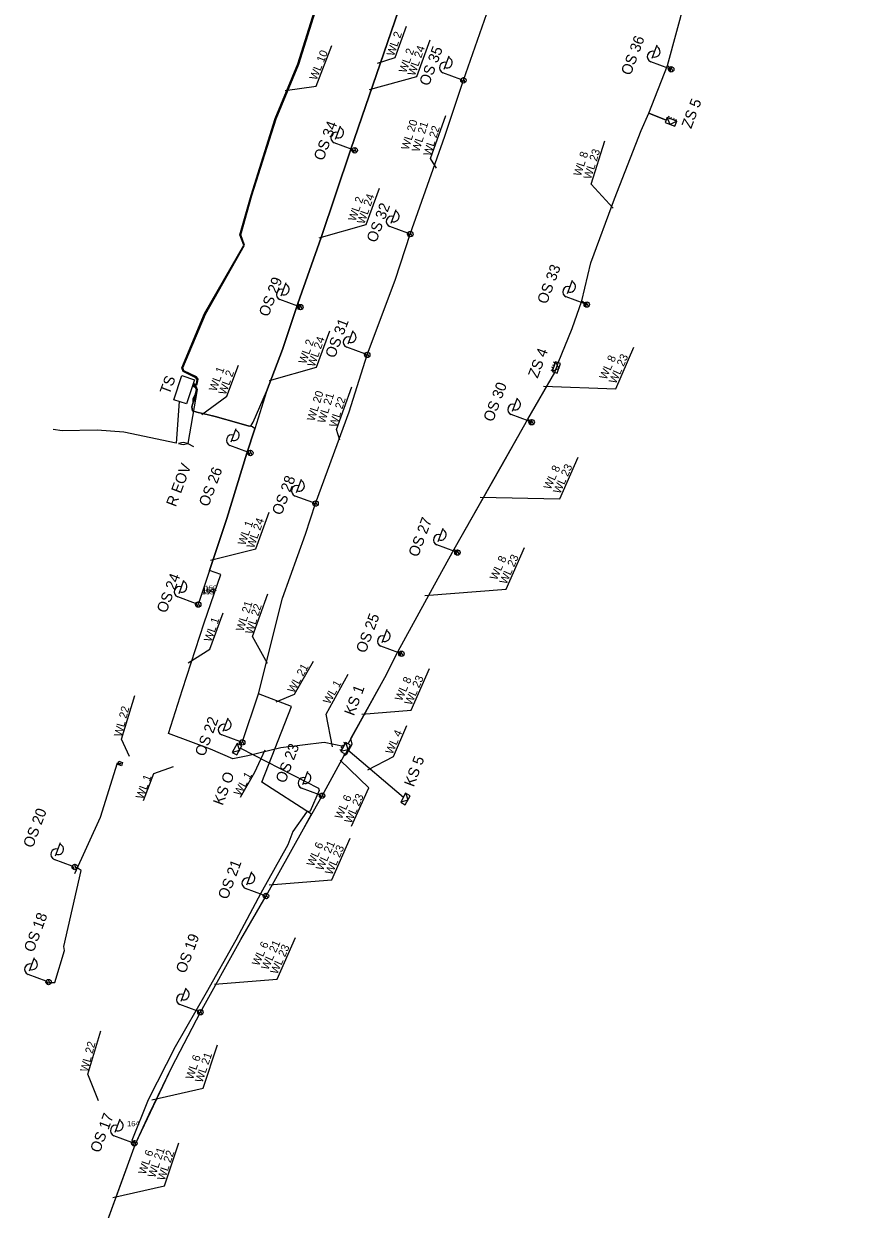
# Model space of a CAD drawing. Extents: x -695448 to -695200, y -1124997 to -1123857.
# Drawn here: x -695445.5 to -695287.6, y -1124601.1 to -1124378.9 of the extents above; entities that cross this region are included whole.
import ezdxf

# ---------------------------------------------------------------- set-up
doc = ezdxf.new("R2010")
doc.units = 0
doc.layers.add('Vrstva 26', color=7, linetype='Continuous')

msp = doc.modelspace()

# ---------------------------------------------------------------- linework, layer by layer
at = {"layer": 'Vrstva 26'}
for p, q in [((-695327.74, -1124385.33), (-695326.82, -1124382.84)), ((-695366.68, -1124387.38), (-695365.75, -1124384.89)), ((-695324.64, -1124387.24), (-695327.99, -1124386)), ((-695324.16, -1124387.42), (-695324.84, -1124386.71)), ((-695324.19, -1124387.93), (-695324.56, -1124387.11)), ((-695323.82, -1124387.8), (-695324.23, -1124386.92)), ((-695363.57, -1124389.3), (-695366.92, -1124388.06)), ((-695363.12, -1124389.98), (-695363.49, -1124389.17)), ((-695362.75, -1124389.86), (-695363.16, -1124388.97)), ((-695387.05, -1124400.51), (-695386.12, -1124398.01)), ((-695383.94, -1124402.42), (-695387.29, -1124401.18)), ((-695384.22, -1124402.55), (-695383.46, -1124402.6)), ((-695383.49, -1124403.11), (-695383.86, -1124402.29)), ((-695383.12, -1124402.98), (-695383.53, -1124402.09)), ((-695376.63, -1124416.21), (-695375.71, -1124413.71)), ((-695373.52, -1124418.12), (-695376.88, -1124416.88)), ((-695373.07, -1124418.81), (-695373.45, -1124417.99)), ((-695372.71, -1124418.68), (-695373.12, -1124417.79)), ((-695397.22, -1124429.89), (-695396.3, -1124427.39)), ((-695343.58, -1124429.4), (-695342.66, -1124426.9)), ((-695394.11, -1124431.8), (-695397.47, -1124430.56)), ((-695394.1, -1124431.3), (-695393.64, -1124431.98)), ((-695393.66, -1124432.49), (-695394.04, -1124431.67)), ((-695393.3, -1124432.36), (-695393.71, -1124431.47)), ((-695340.47, -1124431.31), (-695343.83, -1124430.07)), ((-695340.91, -1124430.82), (-695339.99, -1124431.49)), ((-695340.02, -1124432), (-695340.4, -1124431.18)), ((-695339.66, -1124431.87), (-695340.07, -1124430.98)), ((-695384.7, -1124438.83), (-695383.78, -1124436.34)), ((-695381.59, -1124440.74), (-695384.95, -1124439.5)), ((-695381.14, -1124441.43), (-695381.52, -1124440.61)), ((-695380.78, -1124441.3), (-695381.19, -1124440.41)), ((-695353.89, -1124451.46), (-695352.97, -1124448.96)), ((-695350.78, -1124453.37), (-695354.14, -1124452.13)), ((-695351, -1124452.98), (-695350.3, -1124453.55)), ((-695350.33, -1124454.06), (-695350.71, -1124453.24)), ((-695349.97, -1124453.93), (-695350.38, -1124453.04)), ((-695406.6, -1124457.22), (-695405.67, -1124454.73)), ((-695403.49, -1124459.13), (-695406.84, -1124457.89)), ((-695402.67, -1124459.7), (-695403.08, -1124458.81)), ((-695403.64, -1124459.33), (-695403.01, -1124459.31)), ((-695403.04, -1124459.82), (-695403.41, -1124459.01)), ((-695394.39, -1124466.7), (-695393.46, -1124464.21)), ((-695391.28, -1124468.62), (-695394.63, -1124467.38)), ((-695390.83, -1124469.3), (-695391.2, -1124468.49)), ((-695390.46, -1124469.18), (-695390.87, -1124468.29)), ((-695367.8, -1124475.88), (-695366.88, -1124473.38)), ((-695364.69, -1124477.79), (-695368.05, -1124476.55)), ((-695364.83, -1124477.32), (-695364.22, -1124477.97)), ((-695364.24, -1124478.48), (-695364.62, -1124477.66)), ((-695363.88, -1124478.35), (-695364.29, -1124477.46)), ((-695416.37, -1124485.63), (-695415.45, -1124483.14)), ((-695413.26, -1124487.54), (-695416.62, -1124486.3)), ((-695412.81, -1124488.23), (-695413.19, -1124487.41)), ((-695412.45, -1124488.1), (-695412.86, -1124487.21)), ((-695378.3, -1124494.86), (-695377.38, -1124492.36)), ((-695375.19, -1124496.77), (-695378.55, -1124495.53)), ((-695375.29, -1124496.44), (-695374.71, -1124496.95)), ((-695374.74, -1124497.46), (-695375.12, -1124496.64)), ((-695374.38, -1124497.33), (-695374.79, -1124496.44)), ((-695408.12, -1124511.47), (-695407.19, -1124508.97)), ((-695405.01, -1124513.38), (-695408.36, -1124512.14)), ((-695404.56, -1124514.07), (-695404.93, -1124513.25)), ((-695404.19, -1124513.94), (-695404.6, -1124513.05)), ((-695384.73, -1124514.92), (-695374.35, -1124523.84)), ((-695393.16, -1124521.46), (-695392.24, -1124518.97)), ((-695390.05, -1124523.37), (-695393.41, -1124522.13)), ((-695389.6, -1124524.06), (-695389.98, -1124523.24)), ((-695389.24, -1124523.94), (-695389.65, -1124523.05)), ((-695439.49, -1124534.82), (-695438.57, -1124532.32)), ((-695436.38, -1124536.73), (-695439.74, -1124535.49)), ((-695435.93, -1124537.42), (-695436.31, -1124536.6)), ((-695435.57, -1124537.29), (-695435.98, -1124536.4)), ((-695403.66, -1124540.25), (-695402.74, -1124537.75)), ((-695400.56, -1124542.16), (-695403.91, -1124540.92)), ((-695400.11, -1124542.85), (-695400.48, -1124542.03)), ((-695399.74, -1124542.72), (-695400.15, -1124541.83)), ((-695444.4, -1124556.38), (-695443.48, -1124553.89)), ((-695441.29, -1124558.29), (-695444.65, -1124557.05)), ((-695440.84, -1124558.98), (-695441.22, -1124558.16)), ((-695440.48, -1124558.85), (-695440.89, -1124557.97)), ((-695415.96, -1124562.03), (-695415.04, -1124559.54)), ((-695412.85, -1124563.94), (-695416.21, -1124562.7)), ((-695412.4, -1124564.63), (-695412.78, -1124563.82)), ((-695412.04, -1124564.51), (-695412.45, -1124563.62)), ((-695428.33, -1124586.6), (-695427.41, -1124584.11)), ((-695425.22, -1124588.51), (-695428.58, -1124587.27)), ((-695424.77, -1124589.2), (-695425.15, -1124588.38)), ((-695424.41, -1124589.07), (-695424.82, -1124588.19))]:
    msp.add_line(p, q, dxfattribs=at)
for points in [[(-695325.09, -1124396.92), (-695328.34, -1124395.64), (-695324.84, -1124386.71), (-695321.56, -1124374.49), (-695315.29, -1124355.96), (-695310.83, -1124340.54), (-695308.31, -1124332.94), (-695298.45, -1124305.03), (-695295.16, -1124294), (-695287.62, -1124268.59), (-695300.31, -1124263.86), (-695308.19, -1124258.46), (-695311.18, -1124257.36)], [(-695390.8, -1124468.79), (-695384.48, -1124451.59), (-695381.11, -1124440.92), (-695375.83, -1124426.72), (-695373.04, -1124418.3), (-695366.56, -1124399.91), (-695363.09, -1124389.47), (-695356.09, -1124369.39), (-695352.55, -1124358.94), (-695351.13, -1124358.25), (-695350.8, -1124357.25)], [(-695413.68, -1124446.27), (-695413.27, -1124446.44), (-695413.12, -1124446.31), (-695412.98, -1124445.52), (-695413.24, -1124445.21), (-695415.63, -1124444.02), (-695415.86, -1124443.36), (-695411.6, -1124433.2), (-695404.26, -1124420.34), (-695404.96, -1124418.42), (-695402.89, -1124411.01), (-695398.35, -1124396.64), (-695394.13, -1124386.36), (-695385.53, -1124359.11)], [(-695413.74, -1124446.44), (-695413.24, -1124446.63), (-695412.97, -1124446.41), (-695412.8, -1124445.48), (-695413.13, -1124445.07), (-695415.49, -1124443.9), (-695415.68, -1124443.36), (-695411.44, -1124433.27), (-695404.08, -1124420.35), (-695404.78, -1124418.42), (-695402.71, -1124411.05), (-695398.18, -1124396.7), (-695393.96, -1124386.42), (-695385.36, -1124359.17)], [(-695432.64, -1124611.07), (-695427.6, -1124597.21), (-695424.56, -1124588.76), (-695421.94, -1124583.2), (-695417.73, -1124574.39), (-695412.37, -1124564.12), (-695404.77, -1124550.51), (-695400.08, -1124542.34), (-695393.08, -1124529.78), (-695391.53, -1124527.03), (-695400.84, -1124520.99), (-695395.33, -1124506.85), (-695401.46, -1124504.46), (-695396.99, -1124486.5), (-695392.71, -1124474.55), (-695390.8, -1124468.79), (-695384.48, -1124451.59), (-695381.11, -1124440.92), (-695375.83, -1124426.72), (-695373.04, -1124418.3), (-695366.56, -1124399.91), (-695363.09, -1124389.47), (-695356.09, -1124369.39)], [(-695404.53, -1124513.56), (-695401.46, -1124504.46), (-695396.99, -1124486.5), (-695392.71, -1124474.55), (-695390.8, -1124468.79), (-695384.48, -1124451.59), (-695381.11, -1124440.92), (-695375.83, -1124426.72), (-695373.04, -1124418.3), (-695366.56, -1124399.91), (-695363.09, -1124389.47), (-695356.09, -1124369.39)], [(-695413.77, -1124450.05), (-695413.97, -1124450.66), (-695413.88, -1124451.4), (-695413.01, -1124451.69), (-695411.66, -1124451.99), (-695410.63, -1124452.22), (-695409.6, -1124452.45), (-695405.19, -1124453.71), (-695403.24, -1124454.27), (-695402.83, -1124454.18), (-695402.48, -1124453.54), (-695399.99, -1124447.81), (-695396.97, -1124439.89), (-695394.1, -1124431.3), (-695389.77, -1124418.94), (-695384.22, -1124402.55), (-695381.37, -1124394.21), (-695374.55, -1124374.32)], [(-695374.55, -1124374.32), (-695384.22, -1124402.55), (-695389.77, -1124418.94), (-695394.1, -1124431.3), (-695396.97, -1124439.89), (-695399.99, -1124447.81), (-695402.2, -1124454.81), (-695403.64, -1124459.33), (-695407.43, -1124471.62), (-695412.78, -1124487.72)], [(-695412.37, -1124564.12), (-695404.77, -1124550.51), (-695400.08, -1124542.34), (-695393.08, -1124529.78), (-695389.57, -1124523.55), (-695385.44, -1124515.98), (-695384.93, -1124515.68), (-695383.96, -1124513.88), (-695384.16, -1124512.85), (-695377.82, -1124501.36), (-695375.29, -1124496.44), (-695367.81, -1124482.77), (-695364.83, -1124477.32), (-695356.03, -1124461.84), (-695351, -1124452.98), (-695345.96, -1124444.22), (-695345.34, -1124442.39), (-695342.7, -1124435.97), (-695340.91, -1124430.82), (-695339.23, -1124423.66), (-695334.81, -1124411.65), (-695329.78, -1124398.88), (-695328.34, -1124395.64), (-695324.84, -1124386.71), (-695321.56, -1124374.49)], [(-695379.16, -1124386.28), (-695375.88, -1124385.19), (-695373.78, -1124379.34)], [(-695396.52, -1124391.37), (-695390.68, -1124390.55), (-695387.73, -1124382.92)], [(-695380.67, -1124391.18), (-695371.81, -1124388.73), (-695369.35, -1124381.88)], [(-695368.11, -1124405.94), (-695369.23, -1124404.11), (-695366.39, -1124396.07)], [(-695345.34, -1124442.39), (-695342.7, -1124435.97), (-695340.91, -1124430.82), (-695339.23, -1124423.66), (-695334.81, -1124411.65), (-695329.78, -1124398.88), (-695328.34, -1124395.64), (-695325.09, -1124396.92)], [(-695323.12, -1124397.12), (-695324.37, -1124397.72), (-695324.91, -1124396.44)], [(-695335.04, -1124413.42), (-695339.15, -1124408.93), (-695336.61, -1124400.79)], [(-695390.15, -1124418.97), (-695381.3, -1124416.51), (-695378.84, -1124409.66)], [(-695399.45, -1124445.72), (-695390.59, -1124443.26), (-695388.13, -1124436.41)], [(-695348.08, -1124446.82), (-695334.56, -1124447.26), (-695331.15, -1124439.45)], [(-695412.1, -1124452.13), (-695407.39, -1124448.67), (-695405.23, -1124442.85)], [(-695345.82, -1124442.24), (-695345.2, -1124443.48), (-695346.47, -1124444.05)], [(-695384.7, -1124513.84), (-695377.82, -1124501.36), (-695375.29, -1124496.44), (-695367.81, -1124482.77), (-695364.83, -1124477.32), (-695351, -1124452.98), (-695345.96, -1124444.22)], [(-695413.8, -1124446.61), (-695413.24, -1124446.81), (-695412.97, -1124447.39), (-695414.71, -1124457.54), (-695413.66, -1124458.1)], [(-695413.85, -1124446.76), (-695413.33, -1124446.95), (-695413.14, -1124447.4), (-695413.77, -1124450.05)], [(-695386.26, -1124456.88), (-695386.88, -1124454.93), (-695384.03, -1124446.9)], [(-695416.32, -1124449.68), (-695416.88, -1124457.45), (-695426.71, -1124455.42), (-695431.7, -1124455.05), (-695438.26, -1124455.15), (-695439.94, -1124454.94)], [(-695385.55, -1124514.33), (-695389.21, -1124513.56), (-695397.27, -1124514.55), (-695403.51, -1124516.08), (-695406.28, -1124516.63), (-695410.5, -1124514.84), (-695418.36, -1124511.88), (-695415.71, -1124503.66), (-695411.68, -1124491.14), (-695408.54, -1124482.07), (-695410.67, -1124481.36), (-695407.43, -1124471.62), (-695403.64, -1124459.33), (-695402.2, -1124454.81), (-695402.6, -1124454.44), (-695403.24, -1124454.27), (-695405.19, -1124453.71), (-695409.6, -1124452.45), (-695413.01, -1124451.69), (-695413.88, -1124451.4), (-695413.97, -1124450.66), (-695413.77, -1124450.05)], [(-695359.94, -1124467.6), (-695345, -1124467.88), (-695341.59, -1124460.07)], [(-695410.47, -1124479.38), (-695401.96, -1124477.26), (-695399.5, -1124470.41)], [(-695370.34, -1124486.03), (-695355.07, -1124484.84), (-695351.66, -1124477.03)], [(-695399.83, -1124498.78), (-695402.6, -1124493.71), (-695399.75, -1124485.68)], [(-695414.68, -1124498.65), (-695410.59, -1124496.11), (-695408.13, -1124489.26)], [(-695398.2, -1124505.96), (-695394.77, -1124504.53), (-695391.2, -1124498.34)], [(-695387.62, -1124514.38), (-695388.79, -1124508.24), (-695384.7, -1124500.77)], [(-695382.13, -1124508.24), (-695372.86, -1124507.51), (-695369.45, -1124499.7)], [(-695425.65, -1124516.22), (-695427.13, -1124512.93), (-695424.65, -1124504.77)], [(-695381.03, -1124518.68), (-695376.21, -1124516.19), (-695373.68, -1124510.39)], [(-695405.5, -1124513.75), (-695405.07, -1124515.06), (-695406.41, -1124515.44)], [(-695385.13, -1124513.59), (-695384.73, -1124514.92), (-695386.07, -1124515.26)], [(-695432.64, -1124611.07), (-695424.56, -1124588.76), (-695417.73, -1124574.39), (-695412.37, -1124564.12), (-695404.77, -1124550.51), (-695400.08, -1124542.34), (-695393.08, -1124529.78), (-695389.57, -1124523.55), (-695385.44, -1124515.98), (-695385.37, -1124515.66)], [(-695404.83, -1124514.62), (-695390.26, -1124522.15), (-695390.12, -1124522.58), (-695391.82, -1124526.44), (-695392.51, -1124526.62), (-695395.03, -1124530.26), (-695395.98, -1124532.78), (-695401.05, -1124541.84), (-695405.76, -1124550.6), (-695411.32, -1124560.47), (-695417.11, -1124570.58), (-695422.17, -1124580.53), (-695425.24, -1124588.17), (-695424.74, -1124588.69)], [(-695404.84, -1124523.83), (-695402.19, -1124519.15), (-695400.25, -1124514.92)], [(-695435.88, -1124538.13), (-695431.11, -1124527.58), (-695427.92, -1124517.39), (-695427.43, -1124517.51)], [(-695423.04, -1124524.42), (-695421.11, -1124519.4), (-695417.43, -1124518.1)], [(-695384.04, -1124529.26), (-695380.79, -1124522.06), (-695386.21, -1124516.91)], [(-695373.91, -1124523.07), (-695373.51, -1124524.39), (-695374.85, -1124524.74)], [(-695399.47, -1124540.22), (-695387.74, -1124539.3), (-695384.33, -1124531.49)], [(-695440.81, -1124558.47), (-695440.18, -1124558.53), (-695439.62, -1124558.54), (-695437.82, -1124552.56), (-695437.97, -1124551.78), (-695434.72, -1124537.55), (-695435.26, -1124537.2), (-695435.9, -1124536.9)], [(-695409.72, -1124558.84), (-695398, -1124557.93), (-695394.58, -1124550.12)], [(-695431.49, -1124580.76), (-695433.49, -1124575.76), (-695431.01, -1124567.61)], [(-695421.5, -1124580.52), (-695411.86, -1124578.34), (-695409.17, -1124570.26)], [(-695428.76, -1124598.85), (-695419.12, -1124596.67), (-695416.42, -1124588.58)]]:
    msp.add_lwpolyline(points, dxfattribs=at)
for points in [[(-695323.12, -1124397.12), (-695324.91, -1124396.44), (-695325.27, -1124397.38), (-695323.47, -1124398.06)], [(-695345.83, -1124442.24), (-695346.47, -1124444.05), (-695345.52, -1124444.38), (-695344.88, -1124442.57)], [(-695417.33, -1124449.35), (-695415.83, -1124444.81), (-695413.46, -1124445.6), (-695414.97, -1124450.13)], [(-695413.38, -1124448.34), (-695413.77, -1124449.15), (-695413.77, -1124450.05), (-695413.39, -1124449.24)], [(-695415.58, -1124457.35), (-695416.46, -1124457.54), (-695415.58, -1124457.73), (-695414.71, -1124457.54)], [(-695405.5, -1124513.75), (-695406.41, -1124515.44), (-695405.52, -1124515.91), (-695404.62, -1124514.22)], [(-695385.14, -1124513.59), (-695386.07, -1124515.26), (-695385.2, -1124515.75), (-695384.26, -1124514.08)], [(-695427.64, -1124517.07), (-695426.95, -1124517.31), (-695427.17, -1124517.95), (-695427.87, -1124517.71)], [(-695373.92, -1124523.06), (-695374.85, -1124524.74), (-695373.98, -1124525.23), (-695373.04, -1124523.55)]]:
    msp.add_lwpolyline(points, close=True, dxfattribs=at)
for centre, radius in [((-695324.16, -1124387.42), 0.511), ((-695324.16, -1124387.42), 0.511), ((-695363.09, -1124389.47), 0.511), ((-695363.09, -1124389.47), 0.511), ((-695383.46, -1124402.6), 0.511), ((-695383.46, -1124402.6), 0.511), ((-695373.04, -1124418.3), 0.511), ((-695373.04, -1124418.3), 0.511), ((-695393.64, -1124431.98), 0.511), ((-695393.64, -1124431.98), 0.511), ((-695339.99, -1124431.49), 0.511), ((-695339.99, -1124431.49), 0.511), ((-695381.11, -1124440.92), 0.511), ((-695381.11, -1124440.92), 0.511), ((-695350.3, -1124453.55), 0.511), ((-695350.3, -1124453.55), 0.511), ((-695403.01, -1124459.31), 0.511), ((-695403.01, -1124459.31), 0.511), ((-695390.8, -1124468.79), 0.511), ((-695390.8, -1124468.79), 0.511), ((-695364.22, -1124477.97), 0.511), ((-695364.22, -1124477.97), 0.511), ((-695412.78, -1124487.72), 0.511), ((-695412.78, -1124487.72), 0.511), ((-695374.71, -1124496.95), 0.511), ((-695374.71, -1124496.95), 0.511), ((-695404.53, -1124513.56), 0.511), ((-695404.53, -1124513.56), 0.511), ((-695427.43, -1124517.51), 0.0949), ((-695389.57, -1124523.55), 0.511), ((-695389.57, -1124523.55), 0.511), ((-695435.9, -1124536.91), 0.511), ((-695435.9, -1124536.91), 0.511), ((-695400.08, -1124542.34), 0.511), ((-695400.08, -1124542.34), 0.511), ((-695440.81, -1124558.47), 0.511), ((-695440.81, -1124558.47), 0.511), ((-695412.37, -1124564.12), 0.511), ((-695412.37, -1124564.12), 0.511), ((-695424.74, -1124588.69), 0.511), ((-695424.74, -1124588.69), 0.511)]:
    msp.add_circle(centre, radius, dxfattribs=at)
for centre, radius, start, end in [((-695327.27, -1124384.09), 1.02, 249.0025, 70.4077), ((-695366.2, -1124386.14), 1.02, 249.0025, 70.4077), ((-695327.64, -1124385.04), 1.02, 69.7051, 249.7051), ((-695366.57, -1124387.1), 1.02, 69.7051, 249.7051), ((-695324.36, -1124396.34), 0.285, 147.18, 350.4135), ((-695323.44, -1124396.69), 0.285, 147.18, 350.4135), ((-695386.57, -1124399.26), 1.02, 249.0025, 70.4077), ((-695386.94, -1124400.22), 1.02, 69.7051, 249.7051), ((-695376.16, -1124414.96), 1.02, 249.0025, 70.4077), ((-695376.52, -1124415.92), 1.02, 69.7051, 249.7051), ((-695396.75, -1124428.65), 1.02, 249.0025, 70.4077), ((-695343.11, -1124428.16), 1.02, 249.0025, 70.4077), ((-695397.12, -1124429.6), 1.02, 69.7051, 249.7051), ((-695343.47, -1124429.11), 1.02, 69.7051, 249.7051), ((-695384.23, -1124437.59), 1.02, 249.0025, 70.4077), ((-695384.59, -1124438.54), 1.02, 69.7051, 249.7051), ((-695346.58, -1124443.49), 0.285, 238.3384, 81.5718), ((-695346.25, -1124442.57), 0.285, 238.3384, 81.5718), ((-695353.42, -1124450.21), 1.02, 249.0025, 70.4077), ((-695353.78, -1124451.17), 1.02, 69.7051, 249.7051), ((-695406.49, -1124456.93), 1.02, 69.7051, 249.7051), ((-695406.12, -1124455.98), 1.02, 249.0025, 70.4077), ((-695394.28, -1124466.42), 1.02, 69.7051, 249.7051), ((-695393.91, -1124465.46), 1.02, 249.0025, 70.4077), ((-695367.33, -1124474.63), 1.02, 249.0025, 70.4077), ((-695367.7, -1124475.59), 1.02, 69.7051, 249.7051), ((-695416.26, -1124485.34), 1.02, 69.7051, 249.7051), ((-695415.9, -1124484.39), 1.02, 249.0025, 70.4077), ((-695378.19, -1124494.57), 1.02, 69.7051, 249.7051), ((-695377.83, -1124493.61), 1.02, 249.0025, 70.4077), ((-695407.64, -1124510.23), 1.02, 249.0025, 70.4077), ((-695408.01, -1124511.18), 1.02, 69.7051, 249.7051), ((-695386.09, -1124514.7), 0.285, 228.5657, 71.7991), ((-695385.61, -1124513.84), 0.285, 228.5657, 71.7991), ((-695393.05, -1124521.17), 1.02, 69.7051, 249.7051), ((-695392.69, -1124520.22), 1.02, 249.0025, 70.4077), ((-695439.38, -1124534.53), 1.02, 69.7051, 249.7051), ((-695439.02, -1124533.57), 1.02, 249.0025, 70.4077), ((-695403.19, -1124539.01), 1.02, 249.0025, 70.4077), ((-695403.56, -1124539.96), 1.02, 69.7051, 249.7051), ((-695443.93, -1124555.14), 1.02, 249.0025, 70.4077), ((-695444.29, -1124556.09), 1.02, 69.7051, 249.7051), ((-695415.85, -1124561.74), 1.02, 69.7051, 249.7051), ((-695415.49, -1124560.79), 1.02, 249.0025, 70.4077), ((-695428.22, -1124586.31), 1.02, 69.7051, 249.7051), ((-695427.86, -1124585.36), 1.02, 249.0025, 70.4077)]:
    msp.add_arc(centre, radius, start, end, dxfattribs=at)

# ---------------------------------------------------------------- texts
for s, height, rotation, p in [('WL 2', 1.5, 70.5598, (-695376.13, -1124385.06)), ('OS 36', 2, 69.4105, (-695331.78, -1124388.68)), ('WL 24', 1.5, 70.5598, (-695372.2, -1124388.76)), ('OS 35', 2, 69.4105, (-695369.58, -1124390.66)), ('WL 10', 1.5, 68.1219, (-695390.61, -1124389.57)), ('WL 2', 1.5, 70.5598, (-695373.84, -1124388.21)), ('ZS 5', 2, 69.4105, (-695320.43, -1124398.66)), ('OS 34', 2, 69.4105, (-695389.35, -1124404.67)), ('WL 20', 1.5, 72.4231, (-695373.39, -1124402.64)), ('WL 21', 1.5, 72.4231, (-695371.4, -1124403.02)), ('WL 22', 1.5, 72.4231, (-695369.23, -1124403.78)), ('WL 8', 1.5, 72.2546, (-695341.1, -1124407.56)), ('WL 23', 1.5, 72.2546, (-695339.22, -1124408.14)), ('WL 2', 1.5, 70.5598, (-695383.33, -1124416)), ('WL 24', 1.5, 70.5598, (-695381.68, -1124416.54)), ('OS 32', 2, 69.4105, (-695379.45, -1124420.02)), ('OS 33', 2, 69.4105, (-695347.49, -1124431.55)), ('OS 29', 2, 69.4105, (-695399.64, -1124433.92)), ('OS 31', 2, 69.4105, (-695387.2, -1124441.67)), ('WL 2', 1.5, 70.5598, (-695392.63, -1124442.75)), ('WL 24', 1.5, 70.5598, (-695390.98, -1124443.29)), ('ZS 4', 2, 69.4105, (-695349.19, -1124445.43)), ('WL 8', 1.5, 65.993, (-695336.34, -1124445.69)), ('WL 23', 1.5, 65.993, (-695334.54, -1124446.47)), ('TS', 2, 69.4105, (-695418.18, -1124448.49)), ('WL 1', 1.5, 69.9521, (-695409.42, -1124447.88)), ('WL 2', 1.5, 69.9521, (-695407.64, -1124448.54)), ('WL 20', 1.5, 72.4231, (-695391.03, -1124453.47)), ('OS 30', 2, 69.4105, (-695357.57, -1124453.62)), ('WL 21', 1.5, 72.4231, (-695389.05, -1124453.85)), ('WL 22', 1.5, 72.4231, (-695386.87, -1124454.61)), ('R EOV', 2, 69.4105, (-695416.99, -1124469.53)), ('OS 26', 2, 69.4105, (-695410.88, -1124469.52)), ('WL 8', 1.5, 65.993, (-695346.79, -1124466.31)), ('WL 23', 1.5, 65.993, (-695344.99, -1124467.09)), ('OS 28', 2, 69.4105, (-695397.18, -1124471.11)), ('WL 1', 1.5, 70.5598, (-695404.01, -1124476.74)), ('WL 24', 1.5, 70.5598, (-695402.35, -1124477.29)), ('OS 27', 2, 69.4105, (-695371.61, -1124478.95)), ('WL 8', 1.5, 65.993, (-695356.85, -1124483.27)), ('WL 23', 1.5, 65.993, (-695355.05, -1124484.05)), ('OS 24', 2, 69.4105, (-695418.77, -1124489.45)), ('WL 21', 1.5, 72.4231, (-695404.33, -1124492.86)), ('WL 22', 1.5, 72.4231, (-695402.6, -1124493.39)), ('OS 25', 2, 69.4105, (-695381.44, -1124496.95)), ('WL 1', 1.5, 70.5598, (-695410.34, -1124494.84)), ('WL 21', 1.5, 61.227, (-695394.84, -1124504.42)), ('WL 23', 1.5, 65.993, (-695372.85, -1124506.72)), ('WL 1', 1.5, 60.8883, (-695388.18, -1124506.52)), ('KS 1', 2, 69.4105, (-695383.62, -1124508.7)), ('WL 8', 1.5, 65.993, (-695374.65, -1124505.94)), ('WL 22', 1.5, 75.0133, (-695427.15, -1124512.6)), ('OS 22', 2, 69.4105, (-695411.61, -1124516.32)), ('WL 4', 1.5, 65.993, (-695376.42, -1124515.91)), ('OS 23', 2, 69.4105, (-695396.49, -1124521.33)), ('KS 5', 2, 69.4105, (-695372.4, -1124522.02)), ('WL 1', 1.5, 69.4423, (-695423.14, -1124524.32)), ('KS O', 2, 69.4105, (-695408.2, -1124525.5)), ('WL 1', 1.5, 60.8883, (-695404.92, -1124523.71)), ('WL 23', 1.5, 65.993, (-695384.1, -1124528.88)), ('WL 6', 1.5, 65.993, (-695385.89, -1124528.07)), ('OS 20', 2, 69.4105, (-695443.79, -1124533.47)), ('WL 21', 1.5, 65.993, (-695389.45, -1124537.71)), ('WL 6', 1.5, 65.993, (-695391.18, -1124536.94)), ('WL 23', 1.5, 65.993, (-695387.73, -1124538.51)), ('OS 21', 2, 69.4105, (-695407.3, -1124543.12)), ('OS 18', 2, 69.4105, (-695443.65, -1124553.02)), ('OS 19', 2, 69.4105, (-695415.19, -1124556.98)), ('WL 6', 1.5, 65.993, (-695401.43, -1124555.57)), ('WL 21', 1.5, 65.993, (-695399.7, -1124556.34)), ('WL 23', 1.5, 65.993, (-695397.98, -1124557.14)), ('WL 22', 1.5, 75.0133, (-695433.5, -1124575.44)), ('WL 6', 1.5, 71.1718, (-695413.78, -1124576.85)), ('WL 21', 1.5, 71.1718, (-695412.02, -1124577.45)), ('OS 17', 2, 69.4105, (-695431.24, -1124590.6)), ('WL 6', 1.5, 71.1718, (-695422.65, -1124594.66)), ('WL 21', 1.5, 71.1718, (-695420.89, -1124595.26)), ('WL 22', 1.5, 71.1718, (-695419.1, -1124595.8))]:
    msp.add_text(s, height=height, rotation=rotation, dxfattribs=at).set_placement(p)
for s, p in [('155', (-695412.12, -1124485.82)), ('154', (-695412, -1124485.66)), ('153', (-695411.96, -1124485.47)), ('152', (-695411.55, -1124485.15)), ('164', (-695426.1, -1124585.5))]:
    msp.add_text(s, height=1, dxfattribs=at).set_placement(p)

doc.saveas('drawing.dxf')
